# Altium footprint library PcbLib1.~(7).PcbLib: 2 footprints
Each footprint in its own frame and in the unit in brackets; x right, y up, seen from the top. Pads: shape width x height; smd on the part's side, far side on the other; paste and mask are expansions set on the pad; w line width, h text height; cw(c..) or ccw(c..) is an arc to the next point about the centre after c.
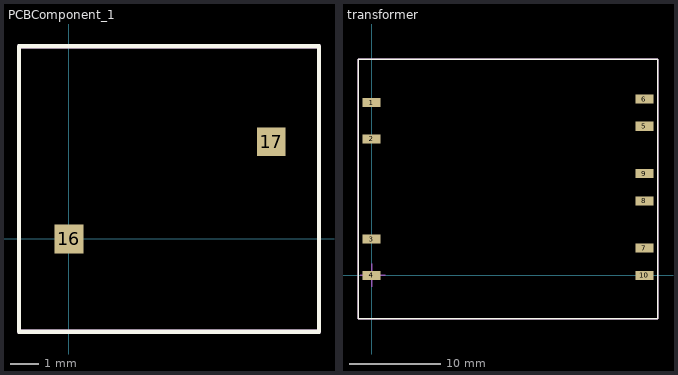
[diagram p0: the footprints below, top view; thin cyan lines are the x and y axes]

## PCBComponent_1 [mm]
pads (2):
  rect 1x1 smd: 16(0,0) 17(7.08,3.4)
Top Overlay:
  lines w0.15: -1.75,-3.25 -1.75,6.75 8.75,6.75 8.75,-3.25 -1.75,-3.25
Top Assembly:
  lines w0.15: -1.75,-3.25 -1.75,6.75 8.75,6.75 8.75,-3.25 -1.75,-3.25
Top Courtyard:
  lines w0.15: -1.75,-3.25 -1.75,6.75 8.75,6.75 8.75,-3.25 -1.75,-3.25
3D body "inductor.stp": height 6.35, standoff -6.48, extent 13.9,1.221 26.6,10.199

## transformer [mm]
pads (10):
  rect 2x1 smd: 1(0,19) 2(0,15) 3(0,4) 4(0,0) 5(30,16.4) 6(30,19.4) 7(30,3) 8(30,8.2) 9(30,11.2) 10(30,0)
Top Overlay:
  lines w0.15: -1.5,-4.8 -1.5,23.8 31.5,23.8 31.5,-4.8 -1.5,-4.8
Top Assembly:
  lines w0.15: -1.5,-4.8 31.5,-4.8 31.5,23.8 -1.5,23.8 -1.5,-4.8
Top Courtyard:
  lines w0.15: -1.5,-4.8 -1.5,23.8 31.5,23.8 31.5,-4.8 -1.5,-4.8
Top Component Center:
  lines w0.15: -1.25,0 1.5,0 ; 0,-1.25 0,1.25
3D body "64.stp": height 17.75, standoff 0, extent -1,-4.8 31,23.8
